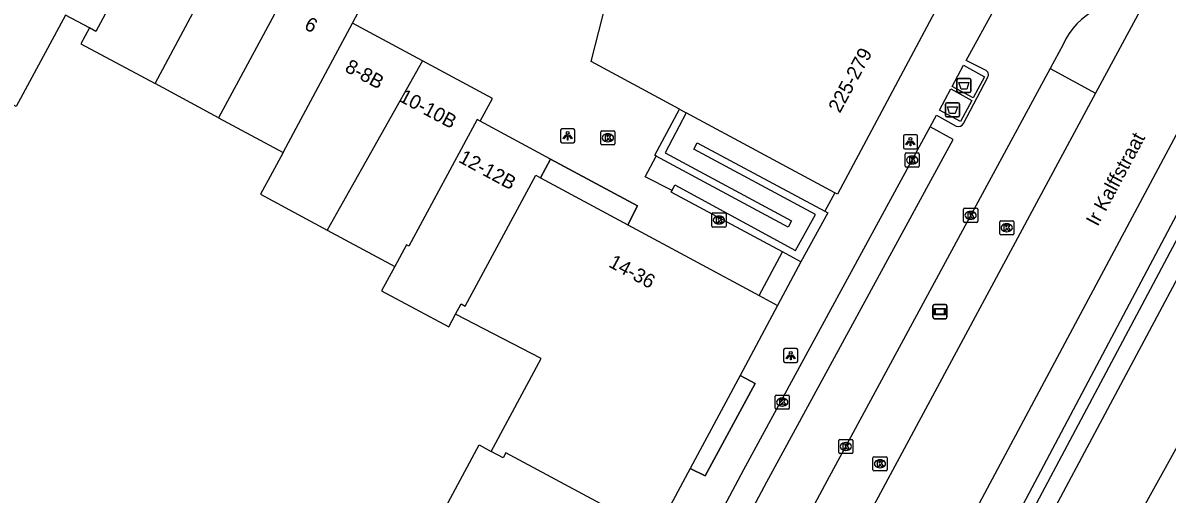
# Model space of a CAD drawing. Extents: x 159489 to 160304, y 383826 to 384530.
# Drawn here: x 159768.9 to 159850, y 384059.8 to 384093.2 of the extents above; entities that cross this region are included whole.
import ezdxf

# ---------------------------------------------------------------- set-up
doc = ezdxf.new("R2010")
doc.units = 0
for name, color, linetype in [('IMGEO_Afval_apart_plaats', 7, 'Continuous'), ('IMGEO_Berm_open', 7, 'Continuous'), ('IMGEO_Haag', 7, 'Continuous'), ('IMGEO_Kolk', 7, 'Continuous'), ('IMGEO_Lichtpunt', 7, 'Continuous'), ('IMGEO_Muur', 7, 'Continuous'), ('IMGEO_Openbare_ruimte_label', 7, 'Continuous'), ('IMGEO_OVBaan_gesloten', 7, 'Continuous'), ('IMGEO_Pand', 7, 'Continuous'), ('IMGEO_Pand_nummerreeks', 7, 'Continuous'), ('IMGEO_Pand_overbouw', 7, 'Continuous'), ('IMGEO_Rijbaan_lokaal_gesloten', 7, 'Continuous'), ('IMGEO_Rijbaan_lokaal_open', 7, 'Continuous'), ('IMGEO_Straatnaambord', 7, 'Continuous'), ('IMGEO_Voetpad_gesloten', 7, 'Continuous'), ('IMGEO_Voetpad_open', 7, 'Continuous')]:
    doc.layers.add(name, color=color, linetype=linetype)

msp = doc.modelspace()

# ---------------------------------------------------------------- linework, layer by layer
at = {"layer": 'IMGEO_Afval_apart_plaats'}
for p, q in [((159835.194, 384089.291), (159835.984, 384089.291)), ((159835.984, 384089.291), (159835.194, 384089.291)), ((159835.094, 384088.391), (159835.094, 384089.191)), ((159835.094, 384089.191), (159835.094, 384088.391)), ((159836.084, 384089.191), (159836.084, 384088.391)), ((159836.084, 384088.391), (159836.084, 384089.191)), ((159835.984, 384088.291), (159835.194, 384088.291)), ((159835.194, 384088.291), (159835.984, 384088.291)), ((159834.28, 384086.662), (159834.28, 384087.462)), ((159834.28, 384087.462), (159834.28, 384086.662)), ((159834.38, 384087.562), (159835.17, 384087.562)), ((159835.17, 384087.562), (159834.38, 384087.562)), ((159835.27, 384087.462), (159835.27, 384086.662)), ((159835.27, 384086.662), (159835.27, 384087.462)), ((159835.17, 384086.562), (159834.38, 384086.562)), ((159834.38, 384086.562), (159835.17, 384086.562))]:
    msp.add_line(p, q, dxfattribs=at)
for points in [[(159835.237, 384089.005), (159835.941, 384089.005), (159835.792, 384088.535), (159835.386, 384088.535), (159835.237, 384089.005)], [(159834.423, 384087.276), (159835.127, 384087.276), (159834.978, 384086.806), (159834.572, 384086.806), (159834.423, 384087.276)]]:
    msp.add_lwpolyline(points, dxfattribs=at)
for centre, start, end in [((159835.194, 384089.191), 90, 180), ((159835.194, 384089.191), 90, 180), ((159835.984, 384089.191), 0, 90), ((159835.984, 384089.191), 360, 90), ((159835.194, 384088.391), 180, 270), ((159835.194, 384088.391), 180, 270), ((159835.984, 384088.391), 270, 0), ((159835.984, 384088.391), 270, 0), ((159834.38, 384087.462), 90, 180), ((159834.38, 384087.462), 90, 180), ((159835.17, 384087.462), 0, 90), ((159835.17, 384087.462), 360, 90), ((159834.38, 384086.662), 180, 270), ((159834.38, 384086.662), 180, 270), ((159835.17, 384086.662), 270, 0), ((159835.17, 384086.662), 270, 0)]:
    msp.add_arc(centre, 0.1, start, end, dxfattribs=at)
at = {"layer": 'IMGEO_Berm_open'}
msp.add_lwpolyline([(159841.694, 384089.989), (159844.928, 384088.249)], dxfattribs=at)
at = {"layer": 'IMGEO_Haag'}
msp.add_lwpolyline([(159834.573, 384049.218), (159855.048, 384087.89)], dxfattribs=at)
at = {"layer": 'IMGEO_Kolk'}
for p, q in [((159809.847, 384084.65), (159809.847, 384085.502)), ((159809.922, 384085.576), (159810.774, 384085.576)), ((159810.335, 384085.356), (159810.36, 384085.356)), ((159810.848, 384085.502), (159810.848, 384084.65)), ((159810.774, 384084.576), (159809.922, 384084.576)), ((159810.358, 384084.796), (159810.333, 384084.796)), ((159831.422, 384083.074), (159831.422, 384083.926)), ((159831.497, 384084), (159832.349, 384084)), ((159831.91, 384083.78), (159831.935, 384083.78)), ((159832.423, 384083.926), (159832.423, 384083.074)), ((159832.349, 384083), (159831.497, 384083)), ((159831.933, 384083.22), (159831.908, 384083.22)), ((159817.721, 384078.819), (159817.721, 384079.671)), ((159817.796, 384079.745), (159818.648, 384079.745)), ((159818.209, 384079.525), (159818.234, 384079.525)), ((159818.722, 384079.671), (159818.722, 384078.819)), ((159835.564, 384079.153), (159835.564, 384080.005)), ((159835.639, 384080.079), (159836.491, 384080.079)), ((159836.052, 384079.859), (159836.077, 384079.859)), ((159836.565, 384080.005), (159836.565, 384079.153)), ((159818.648, 384078.745), (159817.796, 384078.745)), ((159818.232, 384078.965), (159818.207, 384078.965)), ((159836.491, 384079.079), (159835.639, 384079.079)), ((159836.075, 384079.299), (159836.05, 384079.299)), ((159838.125, 384078.271), (159838.125, 384079.123)), ((159838.2, 384079.197), (159839.052, 384079.197)), ((159838.613, 384078.977), (159838.638, 384078.977)), ((159839.126, 384079.123), (159839.126, 384078.271)), ((159839.052, 384078.197), (159838.2, 384078.197)), ((159838.636, 384078.417), (159838.611, 384078.417)), ((159822.209, 384065.911), (159822.209, 384066.763)), ((159822.284, 384066.837), (159823.136, 384066.837)), ((159822.697, 384066.617), (159822.722, 384066.617)), ((159823.21, 384066.763), (159823.21, 384065.911)), ((159823.136, 384065.837), (159822.284, 384065.837)), ((159822.72, 384066.057), (159822.695, 384066.057)), ((159826.716, 384062.763), (159826.716, 384063.615)), ((159826.791, 384063.689), (159827.643, 384063.689)), ((159827.204, 384063.469), (159827.229, 384063.469)), ((159827.717, 384063.615), (159827.717, 384062.763)), ((159827.643, 384062.689), (159826.791, 384062.689)), ((159827.227, 384062.909), (159827.202, 384062.909)), ((159829.214, 384062.464), (159830.066, 384062.464)), ((159829.139, 384061.538), (159829.139, 384062.39)), ((159829.65, 384061.684), (159829.625, 384061.684)), ((159829.627, 384062.244), (159829.652, 384062.244)), ((159830.14, 384062.39), (159830.14, 384061.538)), ((159830.066, 384061.464), (159829.214, 384061.464))]:
    msp.add_line(p, q, dxfattribs=at)
for points in [[(159809.847, 384084.65), (159809.847, 384085.502)], [(159809.922, 384085.576), (159810.774, 384085.576)], [(159810.168, 384085.276), (159810.291, 384085.276), (159810.291, 384085.125), (159810.421, 384085.276), (159810.585, 384085.276), (159810.439, 384085.125), (159810.592, 384084.876), (159810.44, 384084.876), (159810.355, 384085.04), (159810.291, 384084.973), (159810.291, 384084.876), (159810.168, 384084.876), (159810.168, 384085.276)], [(159810.848, 384085.502), (159810.848, 384084.65)], [(159810.774, 384084.576), (159809.922, 384084.576)], [(159831.422, 384083.074), (159831.422, 384083.926)], [(159831.497, 384084), (159832.349, 384084)], [(159831.743, 384083.7), (159831.866, 384083.7), (159831.866, 384083.549), (159831.996, 384083.7), (159832.16, 384083.7), (159832.014, 384083.549), (159832.167, 384083.3), (159832.015, 384083.3), (159831.93, 384083.464), (159831.866, 384083.397), (159831.866, 384083.3), (159831.743, 384083.3), (159831.743, 384083.7)], [(159832.423, 384083.926), (159832.423, 384083.074)], [(159832.349, 384083), (159831.497, 384083)], [(159817.721, 384078.819), (159817.721, 384079.671)], [(159817.796, 384079.745), (159818.648, 384079.745)], [(159818.722, 384079.671), (159818.722, 384078.819)], [(159835.564, 384079.153), (159835.564, 384080.005)], [(159835.639, 384080.079), (159836.491, 384080.079)], [(159835.885, 384079.779), (159836.008, 384079.779), (159836.008, 384079.628), (159836.138, 384079.779), (159836.302, 384079.779), (159836.156, 384079.628), (159836.309, 384079.379), (159836.157, 384079.379), (159836.072, 384079.543), (159836.008, 384079.476), (159836.008, 384079.379), (159835.885, 384079.379), (159835.885, 384079.779)], [(159836.565, 384080.005), (159836.565, 384079.153)], [(159818.648, 384078.745), (159817.796, 384078.745)], [(159818.042, 384079.445), (159818.165, 384079.445), (159818.165, 384079.294), (159818.295, 384079.445), (159818.459, 384079.445), (159818.313, 384079.294), (159818.466, 384079.045), (159818.314, 384079.045), (159818.229, 384079.209), (159818.165, 384079.142), (159818.165, 384079.045), (159818.042, 384079.045), (159818.042, 384079.445)], [(159836.491, 384079.079), (159835.639, 384079.079)], [(159838.125, 384078.271), (159838.125, 384079.123)], [(159838.2, 384079.197), (159839.052, 384079.197)], [(159838.446, 384078.897), (159838.569, 384078.897), (159838.569, 384078.746), (159838.699, 384078.897), (159838.863, 384078.897), (159838.717, 384078.746), (159838.87, 384078.497), (159838.718, 384078.497), (159838.633, 384078.661), (159838.569, 384078.594), (159838.569, 384078.497), (159838.446, 384078.497), (159838.446, 384078.897)], [(159839.126, 384079.123), (159839.126, 384078.271)], [(159839.052, 384078.197), (159838.2, 384078.197)], [(159822.209, 384065.911), (159822.209, 384066.763)], [(159822.284, 384066.837), (159823.136, 384066.837)], [(159822.53, 384066.537), (159822.653, 384066.537), (159822.653, 384066.386), (159822.783, 384066.537), (159822.947, 384066.537), (159822.801, 384066.386), (159822.954, 384066.137), (159822.802, 384066.137), (159822.717, 384066.301), (159822.653, 384066.234), (159822.653, 384066.137), (159822.53, 384066.137), (159822.53, 384066.537)], [(159823.21, 384066.763), (159823.21, 384065.911)], [(159823.136, 384065.837), (159822.284, 384065.837)], [(159826.716, 384062.763), (159826.716, 384063.615)], [(159826.791, 384063.689), (159827.643, 384063.689)], [(159827.037, 384063.389), (159827.16, 384063.389), (159827.16, 384063.238), (159827.29, 384063.389), (159827.454, 384063.389), (159827.308, 384063.238), (159827.461, 384062.989), (159827.309, 384062.989), (159827.224, 384063.153), (159827.16, 384063.086), (159827.16, 384062.989), (159827.037, 384062.989), (159827.037, 384063.389)], [(159827.717, 384063.615), (159827.717, 384062.763)], [(159827.643, 384062.689), (159826.791, 384062.689)], [(159829.214, 384062.464), (159830.066, 384062.464)], [(159829.139, 384061.538), (159829.139, 384062.39)], [(159829.46, 384062.164), (159829.583, 384062.164), (159829.583, 384062.013), (159829.713, 384062.164), (159829.877, 384062.164), (159829.731, 384062.013), (159829.884, 384061.764), (159829.732, 384061.764), (159829.647, 384061.928), (159829.583, 384061.861), (159829.583, 384061.764), (159829.46, 384061.764), (159829.46, 384062.164)], [(159830.14, 384062.39), (159830.14, 384061.538)], [(159830.066, 384061.464), (159829.214, 384061.464)]]:
    msp.add_lwpolyline(points, dxfattribs=at)
for centre, start, end in [((159809.924, 384085.5), 91.55205, 178.44795), ((159809.924, 384085.5), 91.55205, 178.44795), ((159810.772, 384085.5), 1.55205, 88.44795), ((159810.772, 384085.5), 1.55205, 88.44795), ((159809.924, 384084.652), 181.55205, 268.44795), ((159809.924, 384084.652), 181.55205, 268.44795), ((159810.772, 384084.652), 271.55205, 358.44795), ((159810.772, 384084.652), 271.55205, 358.44795), ((159831.499, 384083.924), 91.55205, 178.44795), ((159831.499, 384083.924), 91.55205, 178.44795), ((159832.347, 384083.924), 1.55205, 88.44795), ((159832.347, 384083.924), 1.55205, 88.44795), ((159831.499, 384083.076), 181.55205, 268.44795), ((159831.499, 384083.076), 181.55205, 268.44795), ((159832.347, 384083.076), 271.55205, 358.44795), ((159832.347, 384083.076), 271.55205, 358.44795), ((159817.798, 384079.669), 91.55205, 178.44795), ((159817.798, 384079.669), 91.55205, 178.44795), ((159818.646, 384079.669), 1.55205, 88.44795), ((159818.646, 384079.669), 1.55205, 88.44795), ((159835.641, 384080.003), 91.55205, 178.44795), ((159835.641, 384080.003), 91.55205, 178.44795), ((159836.489, 384080.003), 1.55205, 88.44795), ((159836.489, 384080.003), 1.55205, 88.44795), ((159817.798, 384078.821), 181.55205, 268.44795), ((159817.798, 384078.821), 181.55205, 268.44795), ((159818.646, 384078.821), 271.55205, 358.44795), ((159818.646, 384078.821), 271.55205, 358.44795), ((159835.641, 384079.155), 181.55205, 268.44795), ((159835.641, 384079.155), 181.55205, 268.44795), ((159836.489, 384079.155), 271.55205, 358.44795), ((159836.489, 384079.155), 271.55205, 358.44795), ((159838.202, 384079.121), 91.55205, 178.44795), ((159838.202, 384079.121), 91.55205, 178.44795), ((159839.05, 384079.121), 1.55205, 88.44795), ((159839.05, 384079.121), 1.55205, 88.44795), ((159838.202, 384078.273), 181.55205, 268.44795), ((159838.202, 384078.273), 181.55205, 268.44795), ((159839.05, 384078.273), 271.55205, 358.44795), ((159839.05, 384078.273), 271.55205, 358.44795), ((159822.286, 384066.761), 91.55205, 178.44795), ((159822.286, 384066.761), 91.55205, 178.44795), ((159823.134, 384066.761), 1.55205, 88.44795), ((159823.134, 384066.761), 1.55205, 88.44795), ((159822.286, 384065.913), 181.55205, 268.44795), ((159822.286, 384065.913), 181.55205, 268.44795), ((159823.134, 384065.913), 271.55205, 358.44795), ((159823.134, 384065.913), 271.55205, 358.44795), ((159826.793, 384063.613), 91.55205, 178.44795), ((159826.793, 384063.613), 91.55205, 178.44795), ((159827.641, 384063.613), 1.55205, 88.44795), ((159827.641, 384063.613), 1.55205, 88.44795), ((159826.793, 384062.765), 181.55205, 268.44795), ((159826.793, 384062.765), 181.55205, 268.44795), ((159827.641, 384062.765), 271.55205, 358.44795), ((159827.641, 384062.765), 271.55205, 358.44795), ((159829.216, 384062.388), 91.55205, 178.44795), ((159829.216, 384062.388), 91.55205, 178.44795), ((159830.064, 384062.388), 1.55205, 88.44795), ((159830.064, 384062.388), 1.55205, 88.44795), ((159829.216, 384061.54), 181.55205, 268.44795), ((159829.216, 384061.54), 181.55205, 268.44795), ((159830.064, 384061.54), 271.55205, 358.44795), ((159830.064, 384061.54), 271.55205, 358.44795)]:
    msp.add_arc(centre, 0.0765, start, end, dxfattribs=at)
for centre, major_axis, ratio, start_param, end_param in [((159810.334, 384085.076), (-0.387, 0.002), 0.722429, 4.712389, 7.853982), ((159810.359, 384085.076), (-0.39, 0.002), 0.717154, 1.570796, 4.712389), ((159831.909, 384083.5), (-0.387, 0.002), 0.722429, 4.712389, 7.853982), ((159831.934, 384083.5), (-0.39, 0.002), 0.717154, 1.570796, 4.712389), ((159818.208, 384079.245), (-0.387, 0.002), 0.722429, 4.712389, 7.853982), ((159818.233, 384079.245), (-0.39, 0.002), 0.717154, 1.570796, 4.712389), ((159836.051, 384079.579), (-0.387, 0.002), 0.722429, 4.712389, 7.853982), ((159836.076, 384079.579), (-0.39, 0.002), 0.717154, 1.570796, 4.712389), ((159838.612, 384078.697), (-0.387, 0.002), 0.722429, 4.712389, 7.853982), ((159838.637, 384078.697), (-0.39, 0.002), 0.717154, 1.570796, 4.712389), ((159822.696, 384066.337), (-0.387, 0.002), 0.722429, 4.712389, 7.853982), ((159822.721, 384066.337), (-0.39, 0.002), 0.717154, 1.570796, 4.712389), ((159827.203, 384063.189), (-0.387, 0.002), 0.722429, 4.712389, 7.853982), ((159827.228, 384063.189), (-0.39, 0.002), 0.717154, 1.570796, 4.712389), ((159829.626, 384061.964), (-0.387, 0.002), 0.722429, 4.712389, 7.853982), ((159829.651, 384061.964), (-0.39, 0.002), 0.717154, 1.570796, 4.712389)]:
    msp.add_ellipse(centre, major_axis=major_axis, ratio=ratio, start_param=start_param, end_param=end_param, dxfattribs=at)
at = {"layer": 'IMGEO_Lichtpunt'}
for p, q in [((159806.995, 384085.622), (159806.995, 384084.815)), ((159806.995, 384085.622), (159806.995, 384084.815)), ((159807.897, 384085.717), (159807.089, 384085.717)), ((159807.897, 384085.717), (159807.089, 384085.717)), ((159807.991, 384084.815), (159807.991, 384085.622)), ((159807.991, 384084.815), (159807.991, 384085.622)), ((159831.295, 384085.2), (159831.295, 384084.393)), ((159831.295, 384085.2), (159831.295, 384084.393)), ((159832.197, 384085.295), (159831.389, 384085.295)), ((159832.197, 384085.295), (159831.389, 384085.295)), ((159832.291, 384084.393), (159832.291, 384085.2)), ((159832.291, 384084.393), (159832.291, 384085.2)), ((159807.089, 384084.721), (159807.897, 384084.721)), ((159807.089, 384084.721), (159807.897, 384084.721)), ((159831.389, 384084.299), (159832.197, 384084.299)), ((159831.389, 384084.299), (159832.197, 384084.299)), ((159822.809, 384070.035), (159822.809, 384069.228)), ((159822.809, 384070.035), (159822.809, 384069.228)), ((159823.711, 384070.13), (159822.903, 384070.13)), ((159823.711, 384070.13), (159822.903, 384070.13)), ((159823.805, 384069.228), (159823.805, 384070.035)), ((159823.805, 384069.228), (159823.805, 384070.035)), ((159822.903, 384069.134), (159823.711, 384069.134)), ((159822.903, 384069.134), (159823.711, 384069.134))]:
    msp.add_line(p, q, dxfattribs=at)
for points in [[(159807.369, 384085.286), (159807.408, 384085.258), (159807.22, 384084.996), (159807.182, 384085.023), (159807.369, 384085.286)], [(159807.471, 384085.238), (159807.518, 384085.238), (159807.518, 384084.916), (159807.471, 384084.916), (159807.471, 384085.238)], [(159807.581, 384085.258), (159807.619, 384085.285), (159807.806, 384085.023), (159807.767, 384084.995), (159807.581, 384085.258)], [(159831.669, 384084.864), (159831.708, 384084.836), (159831.52, 384084.574), (159831.482, 384084.601), (159831.669, 384084.864)], [(159831.771, 384084.816), (159831.818, 384084.816), (159831.818, 384084.494), (159831.771, 384084.494), (159831.771, 384084.816)], [(159831.881, 384084.836), (159831.919, 384084.863), (159832.106, 384084.601), (159832.067, 384084.573), (159831.881, 384084.836)], [(159823.183, 384069.699), (159823.222, 384069.671), (159823.034, 384069.409), (159822.996, 384069.436), (159823.183, 384069.699)], [(159823.285, 384069.651), (159823.332, 384069.651), (159823.332, 384069.329), (159823.285, 384069.329), (159823.285, 384069.651)], [(159823.395, 384069.671), (159823.433, 384069.698), (159823.62, 384069.436), (159823.581, 384069.408), (159823.395, 384069.671)]]:
    msp.add_lwpolyline(points, dxfattribs=at)
for centre in [(159807.494, 384085.42), (159831.794, 384084.998), (159823.308, 384069.833)]:
    msp.add_circle(centre, 0.0994, dxfattribs=at)
for centre, start, end in [((159807.089, 384085.622), 90, 180), ((159807.089, 384085.622), 90, 180), ((159807.897, 384085.622), 0, 90), ((159807.897, 384085.622), 0, 90), ((159831.389, 384085.2), 90, 180), ((159831.389, 384085.2), 90, 180), ((159832.197, 384085.2), 0, 90), ((159832.197, 384085.2), 0, 90), ((159807.089, 384084.815), 180, 270), ((159807.089, 384084.815), 180, 270), ((159807.897, 384084.815), 270, 0), ((159807.897, 384084.815), 270, 360), ((159831.389, 384084.393), 180, 270), ((159831.389, 384084.393), 180, 270), ((159832.197, 384084.393), 270, 0), ((159832.197, 384084.393), 270, 360), ((159822.903, 384070.035), 90, 180), ((159822.903, 384070.035), 90, 180), ((159823.711, 384070.035), 0, 90), ((159823.711, 384070.035), 0, 90), ((159822.903, 384069.228), 180, 270), ((159822.903, 384069.228), 180, 270), ((159823.711, 384069.228), 270, 0), ((159823.711, 384069.228), 270, 360)]:
    msp.add_arc(centre, 0.0946, start, end, dxfattribs=at)
at = {"layer": 'IMGEO_Muur'}
for points in [[(159813.766, 384083.773), (159813.666, 384083.835), (159815.417, 384087.11)], [(159815.906, 384086.847), (159814.409, 384084.008), (159823.369, 384079.191), (159823.128, 384078.749), (159813.766, 384083.773)], [(159814.897, 384081.336), (159815.101, 384081.729), (159823.656, 384077.092), (159825.06, 384079.649), (159816.44, 384084.277), (159816.687, 384084.721), (159825.719, 384079.87)], [(159822.717, 384076.982), (159814.84, 384081.228), (159814.897, 384081.336)], [(159825.719, 384079.87), (159825.936, 384079.753), (159824.035, 384076.271)], [(159824.035, 384076.271), (159822.717, 384076.982)]]:
    msp.add_lwpolyline(points, dxfattribs=at)
at = {"layer": 'IMGEO_OVBaan_gesloten'}
for points in [[(159848.384, 384094.67), (159844.928, 384088.249)], [(159852.694, 384089.13), (159852.642, 384089.035), (159831.002, 384048.525), (159825.117, 384037.509)], [(159844.928, 384088.249), (159819.297, 384040.613)]]:
    msp.add_lwpolyline(points, dxfattribs=at)
at = {"layer": 'IMGEO_Pand'}
for points in [[(159815.417, 384087.11), (159809.159, 384090.473), (159814.676, 384112.061)], [(159780.079, 384103.825), (159774.383, 384093.224), (159774.052, 384092.608), (159773.584, 384092.86)], [(159778.243, 384088.92), (159779.168, 384090.651), (159783.759, 384099.239)], [(159788.289, 384096.804), (159783.685, 384088.244), (159782.746, 384086.499)], [(159792.249, 384093.193), (159792.852, 384094.351), (159788.289, 384096.804)], [(159834.642, 384096.101), (159828.467, 384084.527), (159826.63, 384081.083), (159826.448, 384081.181)], [(159773.584, 384092.86), (159771.882, 384093.775), (159768.398, 384087.297), (159767.715, 384087.664)], [(159773.584, 384092.86), (159772.986, 384091.747), (159778.243, 384088.92)], [(159787.322, 384084.039), (159788.25, 384085.766), (159792.249, 384093.193)], [(159797.202, 384090.532), (159792.249, 384093.193)], [(159797.202, 384090.532), (159791.301, 384080.038), (159790.453, 384078.53)], [(159801.286, 384086.256), (159802.155, 384087.87), (159797.202, 384090.532)], [(159782.746, 384086.499), (159778.243, 384088.92)], [(159815.417, 384087.11), (159815.906, 384086.847)], [(159826.448, 384081.181), (159815.906, 384086.847)], [(159782.746, 384086.499), (159787.322, 384084.039)], [(159801.286, 384086.256), (159801.071, 384086.372), (159796.238, 384077.383), (159796.056, 384077.48), (159795.238, 384075.958)], [(159806.283, 384083.563), (159801.286, 384086.256)], [(159787.322, 384084.039), (159786.545, 384082.595), (159785.726, 384081.072), (159790.453, 384078.53)], [(159805.565, 384082.24), (159806.283, 384083.563)], [(159799.545, 384072.565), (159799.942, 384073.305), (159800.234, 384073.149), (159805.24, 384082.416), (159805.565, 384082.24)], [(159805.565, 384082.24), (159811.752, 384078.907)], [(159811.752, 384078.907), (159821.062, 384073.891)], [(159790.453, 384078.53), (159795.238, 384075.958)], [(159795.238, 384075.958), (159794.306, 384074.223), (159799.063, 384071.666), (159799.545, 384072.565)], [(159821.062, 384073.891), (159822.364, 384073.19)], [(159822.364, 384073.19), (159819.714, 384068.212)], [(159802.082, 384062.843), (159805.621, 384069.422), (159799.545, 384072.565)], [(159819.714, 384068.212), (159816.172, 384061.629)], [(159798.849, 384058.909), (159801.215, 384063.308), (159802.082, 384062.843)], [(159813.711, 384057.051), (159803.121, 384062.744), (159802.928, 384062.389), (159802.082, 384062.843)], [(159816.172, 384061.629), (159813.711, 384057.051)]]:
    msp.add_lwpolyline(points, dxfattribs=at)
at = {"layer": 'IMGEO_Pand_overbouw'}
for points in [[(159806.283, 384083.563), (159805.565, 384082.24), (159811.752, 384078.907), (159812.447, 384080.257)], [(159816.172, 384061.629), (159817.243, 384061.099), (159820.789, 384067.656), (159819.714, 384068.212)]]:
    msp.add_lwpolyline(points, close=True, dxfattribs=at)
at = {"layer": 'IMGEO_Rijbaan_lokaal_gesloten'}
for points in [[(159837.077, 384089.883), (159835.74, 384090.56), (159837.844, 384094.373)], [(159842.616, 384091.694), (159841.694, 384089.989)], [(159841.694, 384089.989), (159825.877, 384060.739), (159803.412, 384018.855), (159803.036, 384018.159)], [(159835.552, 384086.088), (159837.252, 384089.326)], [(159833.197, 384085.844), (159833.649, 384086.676), (159835.051, 384085.907)], [(159809.693, 384042.226), (159811.322, 384041.358), (159821.621, 384060.678), (159834.394, 384084.181), (159834.819, 384084.963), (159833.197, 384085.844)]]:
    msp.add_lwpolyline(points, dxfattribs=at)
for centre, radius, start, end in [((159847.383, 384089.533), 5.234, 78.97327, 155.60968), ((159836.971, 384089.544), 0.356, 322.29269, 72.59099), ((159835.21, 384086.252), 0.38, 245.29787, 334.42942)]:
    msp.add_arc(centre, radius, start, end, dxfattribs=at)
at = {"layer": 'IMGEO_Rijbaan_lokaal_open'}
msp.add_lwpolyline([(159860.731, 384081.261), (159820.795, 384009.203)], dxfattribs=at)
at = {"layer": 'IMGEO_Straatnaambord'}
for p, q in [((159833.396, 384072.352), (159833.396, 384073.152)), ((159833.396, 384073.152), (159833.396, 384072.352)), ((159833.496, 384073.252), (159834.286, 384073.252)), ((159834.286, 384073.252), (159833.496, 384073.252)), ((159834.386, 384073.152), (159834.386, 384072.352)), ((159834.386, 384072.352), (159834.386, 384073.152)), ((159834.286, 384072.252), (159833.496, 384072.252)), ((159833.496, 384072.252), (159834.286, 384072.252))]:
    msp.add_line(p, q, dxfattribs=at)
for points in [[(159833.497, 384072.984), (159834.285, 384072.984), (159834.285, 384072.52), (159833.497, 384072.52), (159833.497, 384072.984)], [(159833.562, 384072.919), (159833.562, 384072.585), (159834.22, 384072.585), (159834.22, 384072.919), (159833.562, 384072.919)]]:
    msp.add_lwpolyline(points, dxfattribs=at)
for centre, start, end in [((159833.496, 384073.152), 90, 180), ((159833.496, 384073.152), 90, 180), ((159834.286, 384073.152), 0, 90), ((159834.286, 384073.152), 360, 90), ((159833.496, 384072.352), 180, 270), ((159833.496, 384072.352), 180, 270), ((159834.286, 384072.352), 270, 0), ((159834.286, 384072.352), 270, 0)]:
    msp.add_arc(centre, 0.1, start, end, dxfattribs=at)
at = {"layer": 'IMGEO_Voetpad_gesloten'}
for points in [[(159834.749, 384088.719), (159835.554, 384090.216), (159837.045, 384089.398), (159836.239, 384087.901), (159834.749, 384088.719)], [(159833.849, 384087.045), (159834.654, 384088.543), (159836.144, 384087.725), (159835.339, 384086.228), (159833.849, 384087.045)], [(159814.897, 384081.336), (159812.995, 384082.298), (159813.766, 384083.773)], [(159826.448, 384081.181), (159825.719, 384079.87)]]:
    msp.add_lwpolyline(points, dxfattribs=at)
at = {"layer": 'IMGEO_Voetpad_open'}
for points in [[(159809.693, 384042.226), (159819.995, 384061.553), (159833.197, 384085.844)], [(159806.283, 384083.563), (159812.447, 384080.257), (159811.752, 384078.907)], [(159834.573, 384049.218), (159835.25, 384048.848), (159852.176, 384080.661)], [(159816.486, 384010.875), (159820.158, 384017.866), (159853.355, 384080.02)], [(159821.062, 384073.891), (159822.717, 384076.982)], [(159824.035, 384076.271), (159822.364, 384073.19)], [(159819.714, 384068.212), (159820.789, 384067.656), (159817.243, 384061.099), (159816.172, 384061.629)]]:
    msp.add_lwpolyline(points, dxfattribs=at)

# ---------------------------------------------------------------- texts
at = {"layer": 'IMGEO_Openbare_ruimte_label'}
msp.add_text('Ir Kalffstraat', height=1, rotation=61.89718, dxfattribs=at).set_placement((159845.069, 384078.74))
at = {"layer": 'IMGEO_Pand_nummerreeks'}
for s, rotation, p in [('6', 332.32041, (159788.751, 384092.823)), ('225-279', 61.70685, (159826.795, 384086.773)), ('8-8B', 331.74172, (159791.629, 384089.822)), ('10-10B', 331.98236, (159795.467, 384087.709)), ('12-12B', 331.57556, (159799.689, 384083.393)), ('14-36', 331.62333, (159810.332, 384075.97))]:
    msp.add_text(s, height=1, rotation=rotation, dxfattribs=at).set_placement(p)

doc.saveas('drawing.dxf')
